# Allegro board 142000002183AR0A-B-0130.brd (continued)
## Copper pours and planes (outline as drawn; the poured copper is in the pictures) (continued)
VCC_12P_FAN7_IN on TOP: 34.29,46.6 35.94,46.6 36.2,46.34 36.2,41.77 40.01,37.96 40.01,29.58 39.37,28.94 39.37,25.9 37.21,25.9 36.83,26.28 36.83,27.93 36.96,28.06 37.47,28.06 37.47,37.07 33.66,40.88 33.66,43.8 34.16,44.31 34.16,46.47
VCC_12P_FAN7_OUT on BOTTOM (solid shape): 37.72,55.27 37.72,47.24 38.29,46.67 38.29,44.45 38.15,44.31 38.12,44.31 37.95,44.32 37.77,44.27 36.71,44.27 36.54,44.45 36.54,46.62 36.2,46.96 36.2,55.27 36.27,55.35 37.64,55.35
VCC_12P_FAN7_OUT on TOP: 36.83,46.6 38.1,46.6 38.35,46.34 38.35,44.31 39.12,43.55 39.12,42.66 39.37,42.41 40.89,42.41 46.35,36.95 46.35,29.96 48.13,28.18 48.13,26.15 48.01,26.02 46.02,26.02 44.16,27.89 44.16,28.93 43.79,29.29 43.79,35.19 36.45,42.53 36.45,46.22
VCC_12P_FAN8_IN on BOTTOM (solid shape): 104.08,55.28 104.08,47.48 104.92,46.64 104.92,44.33 104.85,44.25 103.37,44.25 103.25,44.38 103.25,46.48 102.58,47.15 102.58,55.25 102.68,55.35 104,55.35
VCC_12P_FAN8_IN on TOP: 103.25,46.53 104.65,46.53 104.83,46.35 104.83,40.3 101.91,37.38 100.83,37.38 100.61,37.6 100.61,39.56 102.32,41.27 102.32,43.01 102.57,43.26 103.07,43.26 103.07,46.35
VCC_12P_FAN8_IN on TOP: 84.75,29.55 85.84,30.64 94.59,30.64 95.12,30.11 95.12,28.18 94.58,27.64 89.61,27.64 88.98,28.27 84.91,28.27 84.75,28.42
VCC_12P_FAN8_OUT on BOTTOM (solid shape): 106.62,55.25 106.62,47.22 107.21,46.64 107.21,44.35 107.11,44.25 105.3,44.25 105.18,44.37 105.18,46.74 105.17,46.75 105.17,46.87 105.1,46.95 105.1,55.25 105.17,55.33 106.54,55.33
VCC_12P_FAN8_OUT on TOP: 104.65,35.41 104.65,30.35 104.5,30.2 102.51,30.2 101.5,31.21 101.5,32.13 101.2,32.42 101.2,36.32 105.19,40.3 105.19,46.35 105.49,46.65 106.83,46.65 107.15,46.33 107.15,37.91
VCC_CL_FAN7F on TOP (solid shape): 48.09,23.58 48.09,22.84 47.93,22.68 47.93,19.76 47.77,19.6 46.32,19.6 46.18,19.74 46.18,21.85 46.18,21.85 46.18,23.56 46.27,23.65 48.02,23.65
VCC_CL_FAN7R on TOP (solid shape): 39.32,23.6 39.32,20.16 38.82,19.66 37.7,19.66 37.37,19.98 37.37,23.65 37.46,23.74 39.17,23.74
VCC_CL_FAN8F on TOP: 103.21,27.93 104.64,27.93 104.67,27.9 104.67,24.26 104.38,23.98 102.85,23.98 102.85,27.57
VCC_CL_FAN8R on TOP: 80.2,32.42 81.92,32.42 82.63,31.7 82.63,28.42 82.56,28.35 80.13,28.35 79.86,28.62 79.86,32.09
VDD3P3 on TOP: 59.9,24.93 62.82,24.93 64.06,23.69 64.06,22.6 64.28,22.39 67.21,22.39 67.35,22.54 67.35,23.52 67.5,23.67 73.59,23.67 73.9,23.37 73.9,21.39 73.56,21.05 60.55,21.05 59.83,21.77 59.83,24.86
FAN_12V on TOP: 44.24,22.65 45.17,22.65 45.35,22.47 45.35,18.46 45.2,18.31 42.33,18.31 42.22,18.43 42.22,19.28 42.84,19.91 42.84,20.27 44.12,21.55 44.12,22.53
FAN_12V on TOP: 58.56,31.5 60.26,31.5 60.42,31.65 62.46,31.65 62.79,31.31 62.79,30.78 63.19,30.38 66.47,30.38 66.63,30.22 66.63,29.77 66.52,29.65 58.92,29.65 58.35,30.22 58.35,31.29
FAN_12V on TOP: 106.55,35.44 107.64,34.35 107.64,32.94 107.49,32.79 107.49,32.62 107.13,32.26 106.47,32.26 106.38,32.17 105.76,32.17 105.36,32.58 105.36,34.84 105.28,34.91 105.28,35.38 105.34,35.44
FAN_12V on TOP: 123.05,25.52 127.64,25.52 127.76,25.39 127.76,24.25 127.77,24.24 127.77,24.16 130.43,21.5 130.43,18.91 129.92,18.4 122.17,18.4 122.14,18.43 115.29,18.43 114.73,18.99 114.73,21.38 115.3,21.95 115.3,28.67 116.71,30.08 122.29,30.08 122.64,29.73 122.64,25.92
FAN_12V on TOP: 90.36,26.92 93.71,26.92 93.93,26.7 93.93,25.23 93.3,24.61 90.42,24.61 90.22,24.82 90.22,26.78
FAN_12V on TOP: 98.82,26.92 101.04,26.92 102.13,25.84 102.13,24.02 101.95,23.84 99.37,23.84 98.64,24.58 98.64,26.75
FAN_12V on TOP: 40.49,36.39 42.17,36.39 43.01,35.55 43.01,33.9 42.72,33.61 40.44,33.61 40.31,33.75 40.31,36.21
FAN_12V on TOP: 80.4,36.24 82.97,36.24 83.36,35.84 83.36,33.93 82.82,33.39 80.61,33.39 80.18,33.82 80.18,36.01
FAN_12V on TOP: 36.5,35.7 36.72,35.49 36.72,33.71 36.39,33.38 33.63,33.38 33.42,33.59 33.42,34.96 33.43,34.96 33.43,35.18 33.95,35.7
FAN_12V on TOP: 33.75,22.63 36.13,22.63 36.65,22.1 36.65,19.87 36.41,19.63 34.64,19.63 33.46,20.8 33.46,22.34
FAN_12V on V3: 111.13,35.56 111.13,34.39 109.57,32.83 109.57,31.78 111.4,29.95 121.19,29.95 122.96,28.18 122.96,25.88 123.47,25.38 126.72,25.38 128.4,23.7 128.4,19.69 127.44,18.73 48.89,18.73 48.27,18.11 35.41,18.11 33.4,20.13 33.4,35 34.72,36.32 110.37,36.32
FAN_12V_PDU on TOP: 136.53,30.09 143,30.09 145.54,27.55 145.54,17.26 142.49,14.21 137.67,14.21 135.13,11.67 130.43,11.67 129.79,12.31 129.79,15.36 130.87,16.43 130.87,20.24 132.33,21.71 135,21.71 136.14,22.85 136.14,29.71
FAN_12V_PDU on BOTTOM: 136.53,30.09 143,30.09 145.54,27.55 145.54,17.26 142.49,14.21 138.18,14.21 135.64,11.67 130.43,11.67 129.79,12.31 129.79,15.36 130.87,16.43 130.87,20.24 132.33,21.71 135,21.71 136.14,22.85 136.14,29.71
HS_MOS_D on TOP: 130.18,30.85 134.11,30.85 134.87,30.09 134.87,22.98 134.62,22.72 130.94,22.72 130.3,23.36 130.3,24.37 128.91,25.77 123.53,25.77 123.32,25.98 123.32,30.21 125.22,32.12 129.29,32.12 130.05,31.36 130.05,30.98
HS_MOS_D on BOTTOM: 134.37,30.6 134.87,30.09 134.87,22.98 134.62,22.72 130.94,22.72 130.3,23.36 130.3,24.37 128.91,25.77 123.53,25.77 123.32,25.98 123.32,30.21 125.22,32.12 129.29,32.12 130.05,31.36 130.05,30.98 130.18,30.85 130.18,30.6
SW_VDD3P3 on TOP: 66.49,29.16 66.67,28.98 66.67,28.56 66.5,28.39 64.57,28.39 63.15,26.97 58.22,26.97 57.45,27.73 57.45,29.08 57.53,29.16

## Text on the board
Ref Des/Assembly Top: P/N:142000002183A REV:0A
User.6: TOP (COMPONENT_SIDE)                      1
User.7: G2  (GND_LAYER_2)                         2
User.8: V3  (VCC_LAYER_3)                         3
User.9: BOT (SOLDER_SIDE)                         4
User.10: SST (SILKSCREEN_TOP)                      5
User.11: SSB (SILKSCREEN_BOTTOM)                   6
User.12: SMT (SOLDER_MASK_TOP)                     7
User.13: SMB (SOLDER_MASK_BOTTOM)                   8
User.14: DRILL(FINISH HOLE SIZE LIST)               9
User.15: PMT (PASTE_MASK_TOP)                     10
User.16: PMB (PASTE_MASK_BOTTOM)                  11
User.17: DIM (BOARD_DIMENSION)                    12
User.19: FIGURE | SIZE | 10.0 | 12.0 | 40.0 | 67.0 | 118.0 | 125.0 | 138.0 | TOLERANCE | +3.0/-3.0 | +2.0/-2.0 | +3.0/-0.0 | ALL UNITS ARE IN MILS | PLATED | NON-PLATED | QTY | 20 | 666 | 4 | 2 | 3 | DRILL CHART: TOP to BOTTOM
User.26: XY-Check rotation:Aug 08 12:07:22 2018 | XY-Check txt overlap:Aug 08 12:07:04 2018 | XY-Check txt:Aug 08 12:07:31 2018 | XY-Norefdes:Aug 08 12:07:08 2018
